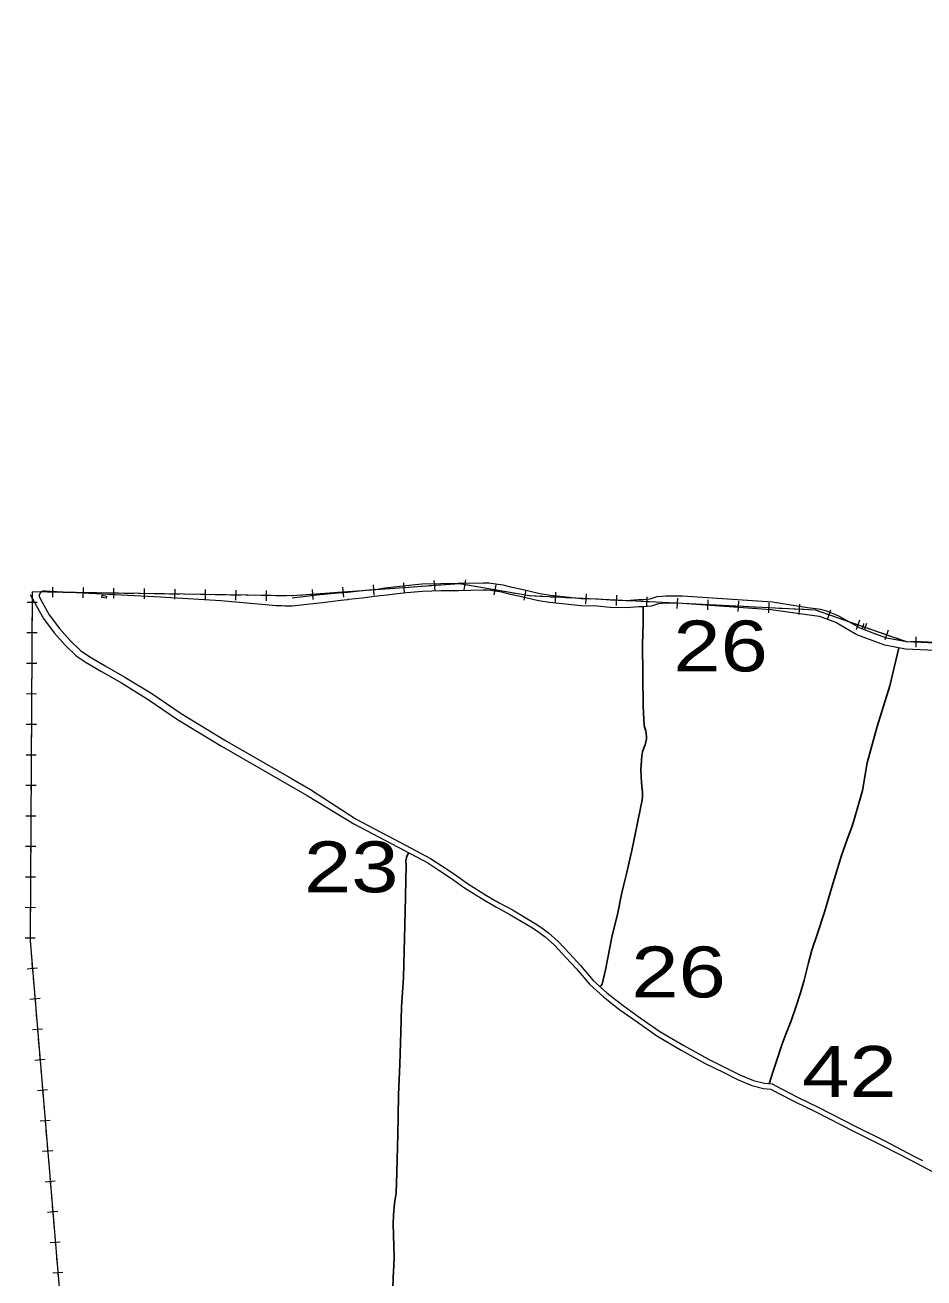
# Model space of a CAD drawing. Extents: x 476989 to 498418, y 4381813 to 4416555.
# Drawn here: x 483846 to 484730, y 4387137 to 4388368 of the extents above; entities that cross this region are included whole.
import ezdxf
from ezdxf.enums import TextEntityAlignment as Align

# ---------------------------------------------------------------- set-up
doc = ezdxf.new("R2010")
doc.units = 0
doc.header["$LTSCALE"] = 20
for name, color, linetype, lineweight in [('13', 7, 'Continuous', 13), ('34', 7, 'Continuous', 13), ('36', 7, 'Continuous', 13), ('38', 7, 'Continuous', 13), ('47', 7, 'Continuous', 13), ('6', 7, 'Continuous', 25)]:
    doc.layers.add(name, color=color, linetype=linetype, lineweight=lineweight)

msp = doc.modelspace()

# ---------------------------------------------------------------- linework, layer by layer
at = {"layer": '34'}
for p, q in [((484279.04, 4387823.02), (484277.33, 4387813.17)), ((483863.03, 4387810.84), (483853.03, 4387811)), ((483878.03, 4387810.61), (483868.03, 4387810.76)), ((483873.11, 4387815.69), (483872.95, 4387805.69)), ((483893.03, 4387810.37), (483883.03, 4387810.53)), ((483908.02, 4387810.14), (483898.03, 4387810.29)), ((483903.1, 4387815.21), (483902.95, 4387805.22)), ((483933.1, 4387814.74), (483932.94, 4387804.75)), ((483963.1, 4387814.27), (483962.94, 4387804.27)), ((483993.09, 4387813.8), (483992.94, 4387803.8)), ((484023.09, 4387813.33), (484022.93, 4387803.33)), ((484053.09, 4387812.86), (484052.93, 4387802.86)), ((484083.08, 4387812.39), (484082.92, 4387802.39)), ((484128.28, 4387813.49), (484129.01, 4387803.51)), ((484163.55, 4387811.04), (484153.58, 4387810.32)), ((484158.21, 4387815.66), (484158.93, 4387805.69)), ((484178.52, 4387812.13), (484168.54, 4387811.4)), ((484193.48, 4387813.22), (484183.5, 4387812.49)), ((484188.13, 4387817.84), (484188.85, 4387807.87)), ((484208.44, 4387814.3), (484198.46, 4387813.58)), ((484223.4, 4387815.39), (484213.42, 4387814.67)), ((484218.05, 4387820.02), (484218.77, 4387810.04)), ((484238.36, 4387816.48), (484228.38, 4387815.76)), ((484253.32, 4387817.57), (484243.34, 4387816.84)), ((484247.97, 4387822.19), (484248.69, 4387812.22)), ((484268.28, 4387818.66), (484258.3, 4387817.93)), ((484283.11, 4387817.24), (484273.26, 4387818.95)), ((484297.89, 4387814.67), (484288.04, 4387816.38)), ((484312.67, 4387812.1), (484302.82, 4387813.81)), ((484308.6, 4387817.88), (484306.89, 4387808.03)), ((484327.45, 4387809.53), (484317.6, 4387811.24)), ((484338.16, 4387812.74), (484336.44, 4387802.89)), ((484367.45, 4387810.74), (484366.95, 4387800.75)), ((483847.94, 4387801.06), (483857.94, 4387801)), ((483852.97, 4387806.03), (483852.91, 4387796.03)), ((483923.02, 4387809.9), (483913.02, 4387810.06)), ((483938.02, 4387809.67), (483928.02, 4387809.82)), ((483953.02, 4387809.43), (483943.02, 4387809.59)), ((483968.02, 4387809.2), (483958.02, 4387809.35)), ((483983.02, 4387808.96), (483973.02, 4387809.12)), ((483998.01, 4387808.73), (483988.01, 4387808.88)), ((484013.01, 4387808.49), (484003.01, 4387808.65)), ((484028.01, 4387808.25), (484018.01, 4387808.41)), ((484043.01, 4387808.02), (484033.01, 4387808.18)), ((484058.01, 4387807.78), (484048.01, 4387807.94)), ((484073, 4387807.55), (484063.01, 4387807.71)), ((484088, 4387807.31), (484078, 4387807.47)), ((484103, 4387807.08), (484093, 4387807.24)), ((484108.44, 4387807.03), (484108, 4387807)), ((484118.67, 4387807.78), (484108.7, 4387807.05)), ((484133.63, 4387808.86), (484123.66, 4387808.14)), ((484148.59, 4387809.95), (484138.62, 4387809.23)), ((484357.21, 4387806.24), (484347.22, 4387806.74)), ((484372.19, 4387805.5), (484362.21, 4387805.99)), ((484387.17, 4387804.75), (484377.19, 4387805.25)), ((484402.16, 4387804), (484392.17, 4387804.5)), ((484397.41, 4387809.25), (484396.91, 4387799.26)), ((484417.14, 4387803.26), (484407.15, 4387803.75)), ((484432.12, 4387802.51), (484422.13, 4387803.01)), ((484427.37, 4387807.75), (484426.88, 4387797.77)), ((484447.1, 4387801.76), (484437.11, 4387802.26)), ((484462.08, 4387801.02), (484452.09, 4387801.51)), ((484457.34, 4387806.26), (484456.84, 4387796.27)), ((484477.06, 4387800.27), (484467.08, 4387800.77)), ((484492.04, 4387799.52), (484482.06, 4387800.02)), ((484487.3, 4387804.77), (484486.8, 4387794.78)), ((484507.03, 4387798.78), (484497.04, 4387799.28)), ((484522.01, 4387798.03), (484512.02, 4387798.53)), ((484517.26, 4387803.27), (484516.76, 4387793.29)), ((484547.22, 4387801.78), (484546.73, 4387791.79)), ((484577.19, 4387800.29), (484576.69, 4387790.3)), ((484607.15, 4387798.8), (484606.65, 4387788.81)), ((483852.88, 4387791.03), (483852.83, 4387781.03)), ((484536.99, 4387797.29), (484527, 4387797.78)), ((484551.97, 4387796.54), (484541.98, 4387797.04)), ((484566.95, 4387795.79), (484556.96, 4387796.29)), ((484581.93, 4387795.05), (484571.95, 4387795.54)), ((484596.91, 4387794.3), (484586.93, 4387794.8)), ((484611.9, 4387793.55), (484601.91, 4387794.05)), ((484640.83, 4387786.79), (484631.39, 4387790.08)), ((484637.75, 4387793.16), (484634.46, 4387783.71)), ((483852.8, 4387776.03), (483852.74, 4387766.03)), ((484655, 4387781.86), (484645.55, 4387785.14)), ((484669.16, 4387776.92), (484659.72, 4387780.21)), ((484666.08, 4387783.29), (484662.8, 4387773.84)), ((484683.33, 4387771.99), (484673.88, 4387775.28)), ((484694.42, 4387773.42), (484691.13, 4387763.98)), ((483847.77, 4387771.06), (483857.77, 4387771)), ((483852.71, 4387761.03), (483852.65, 4387751.03)), ((484697.49, 4387767.05), (484688.05, 4387770.34)), ((484711.66, 4387762.12), (484702.21, 4387765.41)), ((484726.64, 4387761.78), (484716.64, 4387761.93)), ((484721.71, 4387766.85), (484721.56, 4387756.85)), ((483847.59, 4387741.06), (483857.59, 4387741)), ((483852.62, 4387746.03), (483852.56, 4387736.03)), ((483852.53, 4387731.03), (483852.48, 4387721.03)), ((483852.45, 4387716.03), (483852.39, 4387706.03)), ((483847.42, 4387711.06), (483857.42, 4387711)), ((483852.36, 4387701.03), (483852.3, 4387691.03)), ((483847.24, 4387681.06), (483857.24, 4387681)), ((483852.27, 4387686.03), (483852.21, 4387676.03)), ((483852.18, 4387671.03), (483852.13, 4387661.03)), ((483847.07, 4387651.06), (483857.07, 4387651)), ((483852.1, 4387656.03), (483852.04, 4387646.03)), ((483852.01, 4387641.03), (483851.95, 4387631.03)), ((483851.92, 4387626.03), (483851.86, 4387616.03)), ((483846.89, 4387621.06), (483856.89, 4387621.01)), ((483851.83, 4387611.03), (483851.78, 4387601.03)), ((483846.72, 4387591.06), (483856.72, 4387591.01)), ((483851.75, 4387596.04), (483851.69, 4387586.04)), ((483851.66, 4387581.04), (483851.6, 4387571.04)), ((483851.57, 4387566.04), (483851.51, 4387556.04)), ((483846.54, 4387561.06), (483856.54, 4387561.01)), ((483851.48, 4387551.04), (483851.43, 4387541.04)), ((483846.37, 4387531.07), (483856.37, 4387531.01)), ((483851.4, 4387536.04), (483851.34, 4387526.04)), ((483851.31, 4387521.04), (483851.25, 4387511.04)), ((483851.22, 4387506.04), (483851.16, 4387496.04)), ((483846.19, 4387501.07), (483856.19, 4387501.01)), ((483851.13, 4387491.04), (483851.08, 4387481.04)), ((483846.02, 4387471.07), (483856.02, 4387471.01)), ((483851.58, 4387461.06), (483852.41, 4387451.1)), ((483848.26, 4387440.71), (483858.23, 4387441.55)), ((483852.83, 4387446.11), (483853.66, 4387436.15)), ((483854.08, 4387431.17), (483854.91, 4387421.2)), ((483855.33, 4387416.22), (483856.16, 4387406.25)), ((483850.76, 4387410.82), (483860.72, 4387411.65)), ((483856.57, 4387401.27), (483857.41, 4387391.3)), ((483853.26, 4387380.92), (483863.22, 4387381.76)), ((483857.82, 4387386.32), (483858.65, 4387376.36)), ((483859.07, 4387371.37), (483859.9, 4387361.41)), ((483860.32, 4387356.43), (483861.15, 4387346.46)), ((483855.75, 4387351.03), (483865.72, 4387351.86)), ((483861.57, 4387341.48), (483862.4, 4387331.51)), ((483858.25, 4387321.13), (483868.22, 4387321.96)), ((483862.82, 4387326.53), (483863.65, 4387316.56)), ((483864.07, 4387311.58), (483864.9, 4387301.62)), ((483865.31, 4387296.63), (483866.15, 4387286.67)), ((483860.75, 4387291.24), (483870.71, 4387292.07)), ((483866.56, 4387281.69), (483867.39, 4387271.72)), ((483863.24, 4387261.34), (483873.21, 4387262.17)), ((483867.81, 4387266.74), (483868.64, 4387256.77)), ((483869.06, 4387251.79), (483869.89, 4387241.82)), ((483865.74, 4387231.44), (483875.71, 4387232.28)), ((483870.31, 4387236.84), (483871.14, 4387226.88)), ((483871.56, 4387221.89), (483872.39, 4387211.93)), ((483872.8, 4387206.95), (483873.64, 4387196.98)), ((483868.24, 4387201.55), (483878.2, 4387202.38)), ((483874.05, 4387192), (483874.89, 4387182.03)), ((483870.74, 4387171.65), (483880.7, 4387172.48)), ((483875.3, 4387177.05), (483876.13, 4387167.09)), ((483876.55, 4387162.1), (483877.38, 4387152.14)), ((483877.8, 4387147.15), (483878.63, 4387137.19)), ((483873.23, 4387141.76), (483883.2, 4387142.59))]:
    msp.add_line(p, q, dxfattribs=at)
for points in [[(484742, 4388368), (484968, 4388081), (484988, 4388018), (485030, 4387786), (485030, 4387747), (484843, 4387760), (484712, 4387762), (484623, 4387793), (484342, 4387807), (484273, 4387819), (484108.44, 4387807.03)], [(484108, 4387807), (483853, 4387811), (483851, 4387468), (483887, 4387037), (483872.5, 4386448.65)], [(484342.23, 4387806.99), (484342, 4387807), (484332.37, 4387808.67)], [(484626.67, 4387791.72), (484623, 4387793), (484616.89, 4387793.3)], [(483851.05, 4387476.04), (483851, 4387468), (483851.16, 4387466.04)]]:
    msp.add_lwpolyline(points, dxfattribs=at)
at = {"layer": '36'}
for p, q in [((484108.05, 4387627.5), (484126.55, 4387616.86)), ((484108.03, 4387619.81), (484123.22, 4387611.07))]:
    msp.add_line(p, q, dxfattribs=at)
for points in [[(483870.96, 4387811.4), (483866.44, 4387811.67), (483863.59, 4387811.57), (483861.49, 4387811.04), (483860.51, 4387809.56), (483860.05, 4387807.95), (483860.05, 4387806.82), (483860.27, 4387805.88)], [(484108.42, 4387797.03), (484101.21, 4387797.11), (484098.2, 4387797.19), (484092.4, 4387797.41), (484086.08, 4387797.87), (484038.5, 4387802.12), (483979.17, 4387805.81), (483921.64, 4387808.76), (483870.96, 4387811.4)], [(484491.86, 4387799.73), (484486.07, 4387799.96), (484480.46, 4387799.85), (484476.58, 4387799.77), (484472.44, 4387799.57), (484468.51, 4387799.12), (484461.41, 4387796.99), (484454.21, 4387796.32), (484449.24, 4387796.22), (484436.85, 4387795.24), (484421.14, 4387795.78), (484408.38, 4387796.87), (484392.16, 4387797.35), (484377.15, 4387798.88), (484361.67, 4387800.68), (484350.58, 4387802.37), (484339.52, 4387804.85), (484331.1, 4387806.73), (484323.28, 4387808.6), (484314.65, 4387810.64), (484307.63, 4387811.82), (484301.33, 4387812.68), (484296.36, 4387812.58), (484271.93, 4387812.18), (484254.98, 4387812.05), (484236.67, 4387811.54), (484220.97, 4387810.03), (484209.3, 4387808.74), (484201.82, 4387807.75), (484195.07, 4387807.06), (484189.06, 4387806.36), (484177.76, 4387804.99), (484164.03, 4387803.43), (484162.95, 4387803.36), (484156.54, 4387802.4), (484138.3, 4387800.35), (484117.28, 4387798.01), (484108.42, 4387797.03)], [(484174.63, 4387811.68), (484163.41, 4387810.4), (484162.48, 4387810.34), (484153.9, 4387809.75), (484136.02, 4387807.99), (484116.51, 4387805.89), (484108.43, 4387804.72)], [(484492.14, 4387806.72), (484486.14, 4387806.96), (484480.32, 4387806.84), (484476.34, 4387806.76), (484471.87, 4387806.54), (484467.1, 4387806), (484460.07, 4387803.89), (484453.81, 4387803.31), (484448.89, 4387803.21), (484436.69, 4387802.24), (484421.56, 4387802.76), (484408.78, 4387803.86), (484392.62, 4387804.33), (484377.91, 4387805.83), (484362.6, 4387807.61), (484351.87, 4387809.25), (484341.04, 4387811.67), (484332.68, 4387813.54), (484324.9, 4387815.4), (484316.04, 4387817.5), (484308.68, 4387818.74), (484301.73, 4387819.68), (484296.23, 4387819.57), (484271.85, 4387819.17), (484254.85, 4387819.04), (484236.24, 4387818.52), (484220.25, 4387816.99), (484208.34, 4387815.67), (484199.57, 4387814.74), (484192.4, 4387813.48), (484184.31, 4387812.87), (484177.12, 4387811.96), (484174.63, 4387811.68)], [(483851.03, 4387808.55), (483857.01, 4387797.7), (483864.1, 4387784.71), (483874.77, 4387770.68), (483885.4, 4387758.59), (483896.2, 4387748.15), (483906.03, 4387741.65), (483921.28, 4387732.7), (483940.8, 4387721.55), (483967.05, 4387705.4), (483995.93, 4387685.76), (484039.14, 4387659.45), (484108.03, 4387619.81)], [(483860.27, 4387805.88), (483862.88, 4387800.87), (483869.72, 4387788.35), (483879.94, 4387774.91), (483890.24, 4387763.2), (483900.4, 4387753.38), (483909.57, 4387747.32), (483924.63, 4387738.47), (483944.21, 4387727.3), (483970.67, 4387711.01), (483999.55, 4387691.37), (484042.54, 4387665.2), (484108.05, 4387627.5)], [(484798.95, 4387753.61), (484740.73, 4387753.43), (484711.52, 4387754.84), (484691.22, 4387758.64), (484678.76, 4387763.13), (484663.74, 4387768.84), (484653.58, 4387774.86), (484642.8, 4387780.89), (484632.55, 4387784.9), (484626.77, 4387786.76), (484614.38, 4387788.44), (484579.29, 4387793.34), (484491.86, 4387799.73)], [(484798.93, 4387760.7), (484740.89, 4387760.52), (484712.35, 4387761.9), (484693.08, 4387765.5), (484681.23, 4387769.77), (484666.83, 4387775.25), (484657.12, 4387781), (484645.83, 4387787.32), (484634.93, 4387791.59), (484628.34, 4387793.7), (484615.13, 4387795.49), (484580.58, 4387800.8), (484492.14, 4387806.72)], [(484126.55, 4387616.86), (484171.56, 4387587.69), (484220.56, 4387561.88), (484244.55, 4387549.14), (484255.68, 4387541.67), (484268.12, 4387533.64), (484280.94, 4387524.46), (484299.66, 4387512.73), (484312.04, 4387505.62), (484325.17, 4387498.5), (484347.5, 4387485.15), (484353.9, 4387480.89), (484360.39, 4387475.99), (484369.97, 4387467.47), (484381.34, 4387455.3), (484391.96, 4387444.02), (484404.4, 4387429.24), (484417.97, 4387417.02), (484433.78, 4387404.44), (484450.68, 4387392.61), (484469.89, 4387379.04), (484493.44, 4387365.2), (484517.03, 4387352.17), (484534.33, 4387343.66), (484548.49, 4387336.61), (484562.01, 4387330.96), (484572.76, 4387328.16), (484580.5, 4387327.48), (484589.4, 4387322.8), (484605.22, 4387314.52), (484625.5, 4387304.54), (484662.61, 4387285.63)], [(484123.22, 4387611.07), (484169.09, 4387583.22), (484218.18, 4387557.37), (484241.92, 4387544.76), (484252.87, 4387537.41), (484265.25, 4387529.42), (484278.09, 4387520.22), (484297.03, 4387508.36), (484309.55, 4387501.16), (484322.57, 4387494.1), (484344.86, 4387480.78), (484350.95, 4387476.73), (484357.15, 4387472.04), (484366.41, 4387463.82), (484377.62, 4387451.81), (484388.15, 4387440.62), (484400.73, 4387425.69), (484414.67, 4387413.12), (484430.73, 4387400.34), (484447.75, 4387388.44), (484467.12, 4387374.75), (484490.91, 4387360.77), (484514.67, 4387347.64), (484532.07, 4387339.08), (484546.36, 4387331.96), (484560.38, 4387326.12), (484571.88, 4387323.12), (484579.03, 4387322.49), (484587.03, 4387318.28), (484602.91, 4387309.97), (484623.22, 4387299.98), (484660.3, 4387281.08)], [(484660.3, 4387281.08), (484688, 4387267.44), (484716.6, 4387252.46), (484744.57, 4387237.87), (484765.96, 4387228.04), (484785.95, 4387219.5), (484804.94, 4387211.05), (484823.92, 4387201.9), (484841.33, 4387193.76), (484861.92, 4387183.47), (484880.95, 4387174.47), (484900.92, 4387163.88), (484925.9, 4387151.85), (484944.1, 4387141.99), (484964.47, 4387131.61)], [(484662.61, 4387285.63), (484690.3, 4387271.97), (484718.95, 4387256.96), (484728.09, 4387252.19)]]:
    msp.add_lwpolyline(points, dxfattribs=at)
at = {"layer": '38'}
for points in [[(484670.16, 4387780.04), (484669.72, 4387777.82), (484669.1, 4387775.84), (484668.65, 4387774.56)], [(484672.94, 4387780.04), (484672.11, 4387777.17), (484671.45, 4387775.07), (484670.96, 4387773.68)]]:
    msp.add_lwpolyline(points, dxfattribs=at)
at = {"layer": '47'}
msp.add_lwpolyline([(483921.8, 4387807.72), (483926.14, 4387806.91), (483925.75, 4387804.81), (483921.41, 4387805.62)], close=True, dxfattribs=at)
at = {"layer": '6'}
for points in [[(484453.47, 4387780.04), (484453.47, 4387780.1), (484453.58, 4387783.24), (484453.64, 4387789.5), (484453.63, 4387794.48), (484453.5, 4387796.31)], [(484453.47, 4387780.04), (484453.08, 4387759.69), (484453.48, 4387698.54), (484454.48, 4387679.81), (484456.12, 4387674), (484456.9, 4387668.86), (484456.87, 4387666.47), (484455.63, 4387660.65), (484454.55, 4387658.51), (484452.98, 4387653.95), (484452.22, 4387649.97), (484451.33, 4387636.56), (484451.92, 4387623.52)], [(484704.97, 4387756.07), (484696.13, 4387718.73), (484683.45, 4387678.89), (484673.62, 4387643.09), (484669.2, 4387615.95)], [(484451.92, 4387623.52), (484452.86, 4387614.05), (484453.01, 4387610), (484452.55, 4387606.44), (484451.76, 4387601.75), (484447.74, 4387582.4), (484442.3, 4387556.91), (484437.07, 4387533.96), (484434.1, 4387522.04), (484431.88, 4387512.33), (484428.54, 4387495.55), (484422.91, 4387471.62), (484416.7, 4387439.75), (484413.14, 4387425.44), (484411.42, 4387422.97)], [(484577.29, 4387327.76), (484581.51, 4387340.01), (484585.22, 4387351.76), (484589.98, 4387365.78), (484593.96, 4387376.29), (484599.05, 4387389.6), (484604.12, 4387403.9), (484608.08, 4387416.92), (484611.88, 4387429.64), (484616, 4387446.57), (484619.45, 4387459.1), (484624.49, 4387474.46), (484631.82, 4387496.43), (484639.03, 4387521.01), (484648.61, 4387552), (484654.53, 4387568.76), (484658.91, 4387580.79), (484661.5, 4387589.61), (484663.81, 4387597.41), (484669.2, 4387615.95)], [(484223.21, 4387554.7), (484222.02, 4387552.66), (484220.97, 4387549.9), (484220.49, 4387548.37), (484220.38, 4387546.67), (484220.49, 4387542.58), (484219.52, 4387496.61), (484218.07, 4387431.96), (484216.06, 4387403.37), (484215.34, 4387378.04), (484214.43, 4387346.88), (484213.17, 4387316.65), (484212.78, 4387295.39)], [(484212.82, 4387295.28), (484212.47, 4387278.4), (484211.44, 4387240.58), (484210.65, 4387220.54), (484209.3, 4387209.89), (484208.08, 4387198.84), (484207.98, 4387189.84), (484208.12, 4387179.31), (484208.42, 4387167.67), (484208.7, 4387158.03), (484208.44, 4387149.25), (484207.87, 4387137.58), (484207.04, 4387114.72), (484205.45, 4387091.7), (484204.57, 4387075.39), (484204.95, 4387059.47), (484204.36, 4387036.27), (484203.86, 4387018.17), (484202.77, 4387002.21), (484201.65, 4386984.79), (484200.05, 4386972.86), (484199.05, 4386967.22), (484197.58, 4386960.92), (484197.42, 4386960.48)]]:
    msp.add_lwpolyline(points, dxfattribs=at)

# ---------------------------------------------------------------- texts
at = {"layer": '13', "width": 1.25}
for s, p in [('26', (484529.7, 4387732.85)), ('23', (484166.66, 4387515.84)), ('26', (484488.37, 4387412.52)), ('42', (484656.35, 4387314.78))]:
    msp.add_text(s, height=50, dxfattribs=at).set_placement(p, align=Align.CENTER)

doc.saveas('drawing.dxf')
